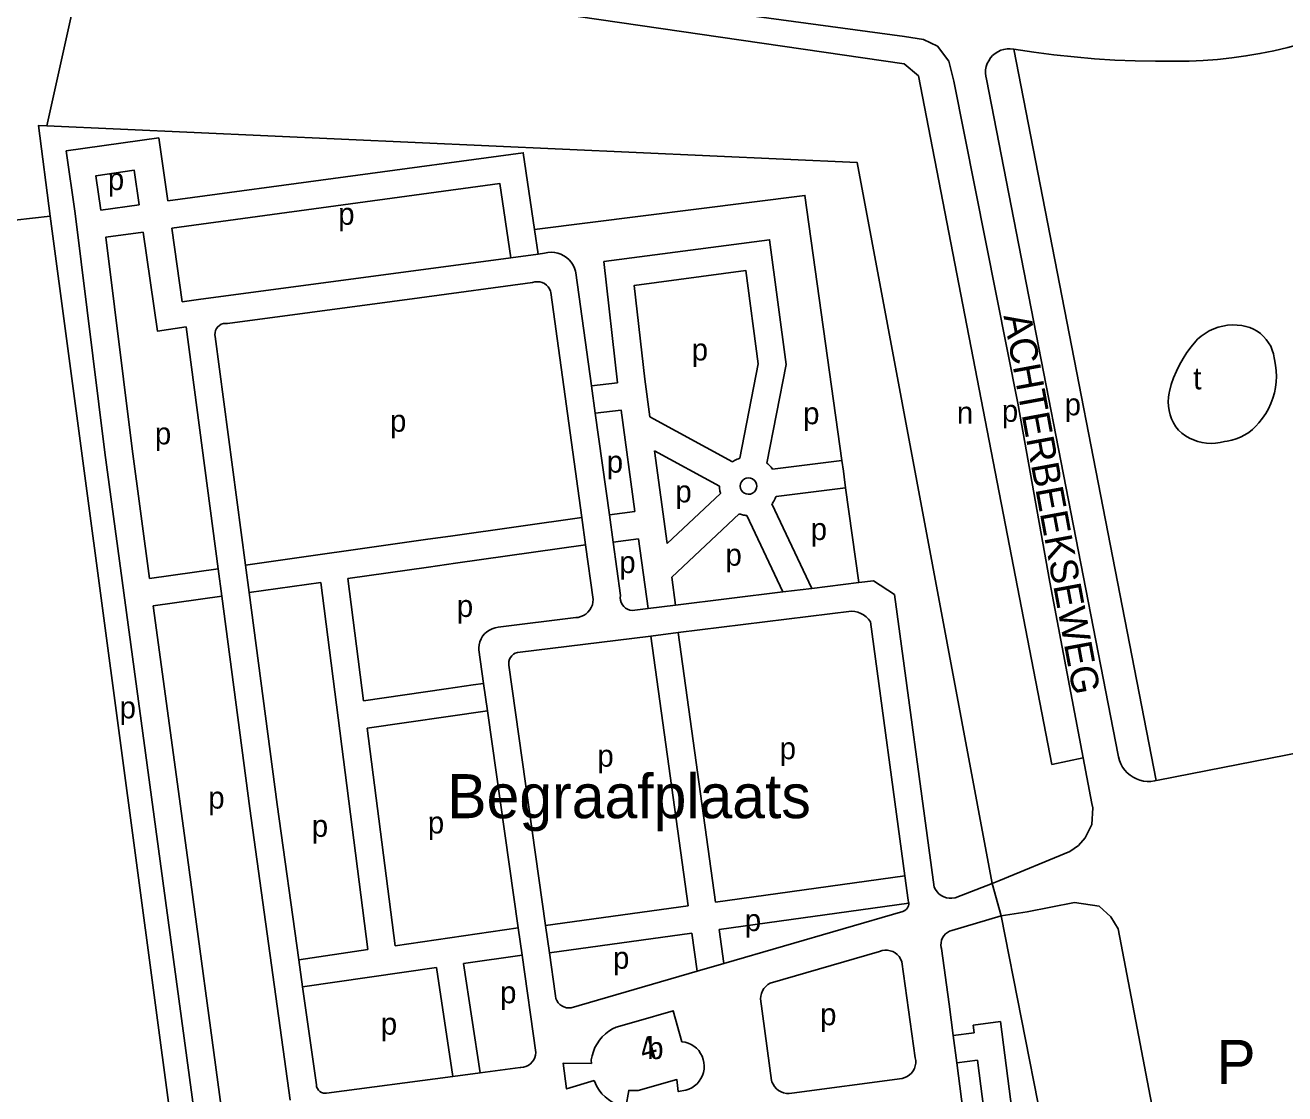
# Model space of a CAD drawing. Extents: x 161093 to 163177, y 379000 to 380904.
# Drawn here: x 162389.1 to 162617.8, y 379974.6 to 380168.6 of the extents above; entities that cross this region are included whole.
import ezdxf

# ---------------------------------------------------------------- set-up
doc = ezdxf.new("R2010")
doc.units = 0
for name, color, linetype in [('BLT_Basislijn', 7, 'Continuous'), ('BLT_Bebouwing', 7, 'Continuous'), ('BLT_Centroide', 7, 'Continuous'), ('BLT_Huisnummer', 7, 'Continuous'), ('BLT_Straatnaam', 7, 'Continuous'), ('BLT_Tekst_parkeren', 7, 'Continuous'), ('BLT_Terrein_beschrifting', 7, 'Continuous')]:
    doc.layers.add(name, color=color, linetype=linetype)

msp = doc.modelspace()

# ---------------------------------------------------------------- linework, layer by layer
at = {"layer": 'BLT_Basislijn'}
for p, q in [((162393.01, 380150.32), (162399.89, 380181.38)), ((162568.58, 380164.26), (162594.45, 380031.45)), ((162563.63, 380158.8), (162587.53, 380036.08)), ((162356.72, 380129.99), (162393.61, 380133.91)), ((162393.61, 380133.91), (162426.07, 379890.63)), ((162481.58, 380131.49), (162482.24, 380127.06)), ((162477.28, 380126.39), (162482.24, 380127.06)), ((162482.24, 380127.06), (162483.39, 380127.21)), ((162420.51, 380118.81), (162477.28, 380126.39)), ((162489.08, 380123.66), (162491.92, 380103.11)), ((162460.67, 380119.12), (162481.21, 380121.88)), ((162484.53, 380120.06), (162490.16, 380079.23)), ((162425.83, 380114.44), (162455.71, 380118.45)), ((162455.71, 380118.45), (162460.67, 380119.12)), ((162418.3, 380113.85), (162424.11, 380069.88)), ((162423.58, 380112.08), (162429.06, 380070.55)), ((162527.23, 380106.99), (162523.77, 380089.07)), ((162501.58, 380104.32), (162502.51, 380097.5)), ((162491.92, 380103.11), (162496.62, 380103.7)), ((162491.92, 380103.11), (162492.6, 380098.15)), ((162492.6, 380098.15), (162495.15, 380079.68)), ((162403.52, 380091.01), (162413.58, 380016.82)), ((162408.47, 380091.69), (162411.66, 380068.17)), ((162490.16, 380079.23), (162466.73, 380075.9)), ((162490.16, 380079.23), (162490.84, 380074.27)), ((162495.15, 380079.68), (162499.8, 380080.31)), ((162495.15, 380079.68), (162495.83, 380074.73)), ((162461.78, 380075.2), (162429.06, 380070.55)), ((162461.78, 380075.2), (162466.73, 380075.9)), ((162490.84, 380074.27), (162467.23, 380070.92)), ((162490.84, 380074.27), (162492.21, 380064.35)), ((162495.83, 380074.73), (162500.47, 380075.35)), ((162495.83, 380074.73), (162497.17, 380065.03)), ((162500.47, 380075.35), (162502.2, 380062.67)), ((162424.11, 380069.88), (162411.66, 380068.17)), ((162424.11, 380069.88), (162424.76, 380064.93)), ((162429.06, 380070.55), (162429.72, 380065.6)), ((162462.28, 380070.22), (162447.68, 380068.15)), ((162462.28, 380070.22), (162467.23, 380070.92)), ((162442.73, 380067.44), (162429.72, 380065.6)), ((162442.73, 380067.44), (162451.31, 380000.75)), ((162447.68, 380068.15), (162450.53, 380045.95)), ((162531.89, 380066.35), (162540.46, 380067.41)), ((162540.46, 380067.41), (162543.09, 380067.74)), ((162543.09, 380067.74), (162546.93, 380065.21)), ((162429.72, 380065.6), (162434.8, 380027.08)), ((162507.16, 380063.29), (162526.68, 380065.71)), ((162526.68, 380065.71), (162528.77, 380065.96)), ((162528.77, 380065.96), (162529.8, 380066.09)), ((162529.8, 380066.09), (162531.89, 380066.35)), ((162546.93, 380065.21), (162554.13, 380012.11)), ((162424.76, 380064.93), (162412.33, 380063.21)), ((162412.33, 380063.21), (162418.54, 380017.49)), ((162424.76, 380064.93), (162429.85, 380026.4)), ((162499.78, 380062.37), (162502.2, 380062.67)), ((162502.2, 380062.67), (162507.16, 380063.29)), ((162474.94, 380059.29), (162489.04, 380061.04)), ((162507.66, 380058.31), (162539.15, 380062.21)), ((162502.69, 380057.69), (162507.66, 380058.31)), ((162507.66, 380058.31), (162514.4, 380009.39)), ((162542.56, 380060.28), (162548.81, 380014.13)), ((162478.45, 380054.69), (162502.69, 380057.69)), ((162502.69, 380057.69), (162509.44, 380008.7)), ((162472.32, 380049.08), (162471.46, 380055.17)), ((162483.58, 380005.14), (162476.9, 380052.43)), ((162472.32, 380049.08), (162470.43, 380048.81)), ((162473.02, 380044.14), (162472.32, 380049.08)), ((162465.49, 380048.1), (162450.53, 380045.95)), ((162465.49, 380048.1), (162470.43, 380048.81)), ((162473.02, 380044.14), (162451.17, 380040.99)), ((162478.59, 380004.7), (162473.02, 380044.14)), ((162451.17, 380040.99), (162456.26, 380001.47)), ((162582.76, 380027.31), (162581.2, 380035.59)), ((162594.8, 380031.54), (162594.45, 380031.45)), ((162429.85, 380026.4), (162437.2, 379973.41)), ((162434.8, 380027.08), (162438.75, 379998.93)), ((162418.54, 380017.49), (162424.67, 379972.19)), ((162548.81, 380014.13), (162514.4, 380009.39)), ((162548.81, 380014.13), (162549.41, 380009.71)), ((162564.67, 380012.78), (162557.94, 380010.17)), ((162565.87, 380013.25), (162564.67, 380012.78)), ((162564.67, 380012.78), (162566.32, 380006.89)), ((162509.44, 380008.7), (162483.58, 380005.14)), ((162549.51, 380009.18), (162515.08, 380004.43)), ((162548.44, 380007.68), (162515.93, 379998.25)), ((162566.32, 380006.89), (162557.37, 380004.24)), ((162566.32, 380006.89), (162582.22, 379925.74)), ((162478.59, 380004.7), (162456.26, 380001.47)), ((162479.29, 379999.75), (162478.59, 380004.7)), ((162484.28, 380000.19), (162483.58, 380005.14)), ((162510.12, 380003.75), (162484.28, 380000.19)), ((162510.12, 380003.75), (162511.08, 379996.84)), ((162515.08, 380004.43), (162515.93, 379998.25)), ((162556.84, 379990.86), (162555.48, 380000.94)), ((162451.31, 380000.75), (162438.75, 379998.93)), ((162438.75, 379998.93), (162439.45, 379993.98)), ((162479.29, 379999.75), (162468.69, 379998.22)), ((162481.79, 379982.08), (162479.29, 379999.75)), ((162485.33, 379992.78), (162484.28, 380000.19)), ((162524.38, 379994.67), (162544.19, 380000.42)), ((162463.74, 379997.5), (162439.45, 379993.98)), ((162463.74, 379997.5), (162466.74, 379977.73)), ((162468.69, 379998.22), (162471.7, 379978.39)), ((162511.08, 379996.84), (162488.22, 379990.21)), ((162515.93, 379998.25), (162511.08, 379996.84)), ((162548.26, 379998.54), (162550.71, 379981.13)), ((162439.45, 379993.98), (162441.94, 379976.19)), ((162522.62, 379991.79), (162524.6, 379976.99)), ((162556.84, 379990.86), (162557.58, 379985.16)), ((162566.17, 379987.69), (162561.21, 379987.05)), ((162566.17, 379987.69), (162571.89, 379943.06)), ((162557.58, 379985.16), (162561.39, 379985.63)), ((162557.58, 379985.16), (162558.23, 379980.21)), ((162561.21, 379987.05), (162561.39, 379985.63)), ((162558.23, 379980.21), (162562.02, 379980.67)), ((162562.02, 379980.67), (162566.09, 379949.01)), ((162466.74, 379977.73), (162471.7, 379978.39)), ((162471.7, 379978.39), (162478.95, 379979.34)), ((162558.23, 379980.21), (162562.37, 379948.61)), ((162443.76, 379974.71), (162466.74, 379977.73)), ((162548.34, 379977.37), (162528.31, 379974.67))]:
    msp.add_line(p, q, dxfattribs=at)
for points in [[(162581.2, 380035.59), (162575.16, 380067.5), (162569.32, 380100), (162557.73, 380158.47), (162556.8, 380162.08), (162554.73, 380164.8), (162552.18, 380166.04), (162548.77, 380166.55), (162469, 380177.37), (162400.95, 380186.18)], [(162581.2, 380035.59), (162575.52, 380034.39), (162551.3, 380159.41), (162548.68, 380161.62), (162449.03, 380176.12), (162399.89, 380181.38)], [(162600.42, 380162.11), (162603.01, 380162.22), (162605.59, 380162.41), (162608.17, 380162.68), (162610.74, 380163.03), (162613.29, 380163.46), (162615.83, 380163.97), (162618.36, 380164.55), (162620.86, 380165.22), (162623.34, 380165.95), (162625.8, 380166.77), (162628.24, 380167.66), (162630.22, 380168.45)], [(162568.58, 380164.26), (162567.94, 380164.34), (162567.36, 380164.32), (162566.78, 380164.22), (162566.22, 380164.05), (162565.68, 380163.8), (162565.19, 380163.48), (162564.74, 380163.1), (162564.36, 380162.66), (162564.03, 380162.17), (162563.77, 380161.64), (162563.59, 380161.09), (162563.48, 380160.51), (162563.46, 380159.92), (162563.51, 380159.34), (162563.63, 380158.8)], [(162568.58, 380164.26), (162572.23, 380163.71), (162575.89, 380163.24), (162579.56, 380162.84), (162583.24, 380162.53), (162586.92, 380162.29), (162590.61, 380162.14), (162594.3, 380162.06), (162597.99, 380162.07), (162600.42, 380162.11)], [(162393.61, 380133.91), (162391.47, 380150.39), (162393.01, 380150.32)], [(162393.01, 380150.32), (162540.14, 380143.69), (162564.67, 380012.78)], [(162414.97, 380136.7), (162413.33, 380148.15), (162396.53, 380145.77)], [(162396.53, 380145.77), (162398.12, 380134.41)], [(162414.97, 380136.7), (162479.51, 380145.46), (162481.58, 380131.49)], [(162409.75, 380135.99), (162408.84, 380142.29), (162401.91, 380141.29), (162402.78, 380135.04)], [(162415.68, 380131.75), (162475.29, 380139.84), (162477.28, 380126.39)], [(162402.78, 380135.04), (162409.75, 380135.99)], [(162481.58, 380131.49), (162530.67, 380137.69), (162537.37, 380089.6)], [(162403.52, 380091.01), (162398.12, 380134.41)], [(162417.6, 380118.38), (162415.68, 380131.75)], [(162408.47, 380091.69), (162403.7, 380130.12), (162410.51, 380131.05)], [(162410.51, 380131.05), (162413.07, 380113.07), (162418.3, 380113.85)], [(162496.62, 380103.7), (162494.17, 380125.68), (162524.26, 380129.66), (162527.23, 380106.99)], [(162483.39, 380127.21), (162483.98, 380127.34), (162484.59, 380127.38), (162485.19, 380127.34), (162485.78, 380127.22), (162486.35, 380127.03), (162486.89, 380126.76), (162487.39, 380126.42), (162487.85, 380126.02), (162488.24, 380125.57), (162488.57, 380125.06), (162488.83, 380124.52), (162489.02, 380123.94), (162489.08, 380123.66)], [(162518.83, 380089.99), (162522.17, 380107.11), (162519.95, 380124.05), (162499.68, 380121.37), (162501.58, 380104.32)], [(162481.21, 380121.88), (162481.64, 380121.99), (162482.09, 380122.03), (162482.54, 380121.99), (162482.97, 380121.87), (162483.37, 380121.68), (162483.73, 380121.42), (162484.04, 380121.09), (162484.29, 380120.72), (162484.46, 380120.31), (162484.53, 380120.06)], [(162420.51, 380118.81), (162417.6, 380118.38)], [(162425.83, 380114.44), (162425.44, 380114.47), (162425.05, 380114.43), (162424.67, 380114.3), (162424.33, 380114.11), (162424.04, 380113.85), (162423.8, 380113.53), (162423.63, 380113.18), (162423.54, 380112.79), (162423.53, 380112.4), (162423.58, 380112.08)], [(162601.97, 380111.58), (162602.64, 380112.15), (162603.35, 380112.65), (162604.1, 380113.1), (162604.9, 380113.47), (162605.72, 380113.76), (162606.57, 380113.98), (162607.43, 380114.12), (162608.3, 380114.18), (162609.18, 380114.17), (162610.03, 380114.07)], [(162610.03, 380114.07), (162610.75, 380113.93), (162611.46, 380113.71), (162612.14, 380113.41), (162612.79, 380113.05), (162613.39, 380112.61), (162613.94, 380112.11), (162614.44, 380111.56), (162614.87, 380110.96), (162615.24, 380110.31), (162615.53, 380109.63), (162615.75, 380108.92), (162615.89, 380108.19), (162615.93, 380107.88)], [(162596.85, 380102.11), (162597.2, 380103.37), (162597.62, 380104.6), (162598.12, 380105.8), (162598.69, 380106.97), (162599.33, 380108.1), (162600.04, 380109.19), (162600.81, 380110.23), (162601.65, 380111.23), (162601.97, 380111.58)], [(162615.93, 380107.88), (162616.12, 380106.88), (162616.24, 380105.87), (162616.28, 380104.85), (162616.24, 380103.84), (162616.12, 380102.83), (162615.91, 380101.83), (162615.63, 380100.86), (162615.28, 380099.9), (162614.85, 380098.98), (162614.35, 380098.1), (162613.78, 380097.26), (162613.12, 380096.43)], [(162598.51, 380095.06), (162598.02, 380095.7), (162597.61, 380096.39), (162597.26, 380097.11), (162596.99, 380097.87), (162596.79, 380098.65), (162596.67, 380099.44), (162596.63, 380100.25), (162596.67, 380101.05), (162596.79, 380101.85), (162596.85, 380102.11)], [(162492.6, 380098.15), (162497.29, 380098.74), (162499.8, 380080.31)], [(162502.51, 380097.5), (162517.5, 380089.35)], [(162606.86, 380093.04), (162606.06, 380092.84), (162605.25, 380092.72), (162604.43, 380092.68), (162603.61, 380092.71), (162602.79, 380092.83), (162601.99, 380093.02), (162601.21, 380093.3), (162600.47, 380093.64), (162599.76, 380094.06), (162599.09, 380094.54), (162598.51, 380095.06)], [(162613.12, 380096.43), (162612.56, 380095.78), (162611.93, 380095.2), (162611.26, 380094.67), (162610.54, 380094.21), (162609.77, 380093.82), (162608.98, 380093.5), (162608.16, 380093.26), (162607.32, 380093.1), (162606.86, 380093.04)], [(162503.35, 380091.32), (162505.64, 380074.48)], [(162503.35, 380091.32), (162515.14, 380084.93)], [(162517.5, 380089.35), (162517.68, 380089.46), (162517.88, 380089.58), (162518.09, 380089.69), (162518.33, 380089.8), (162518.58, 380089.9), (162518.83, 380089.99)], [(162523.77, 380089.07), (162523.9, 380088.96), (162523.99, 380088.88), (162524.11, 380088.77), (162524.21, 380088.66), (162524.34, 380088.54), (162524.51, 380088.34), (162524.65, 380088.16), (162524.78, 380087.99)], [(162524.78, 380087.99), (162537.37, 380089.6)], [(162537.37, 380089.6), (162537.64, 380087.62)], [(162521.92, 380084.92), (162521.88, 380085.27), (162521.75, 380085.62), (162521.51, 380085.96), (162521.17, 380086.22), (162520.77, 380086.38), (162520.36, 380086.42), (162519.99, 380086.36), (162519.67, 380086.22), (162519.4, 380086.02), (162519.15, 380085.72), (162518.98, 380085.35), (162518.92, 380084.92), (162518.98, 380084.5), (162519.15, 380084.13), (162519.4, 380083.83), (162519.67, 380083.63), (162519.99, 380083.49), (162520.36, 380083.43), (162520.77, 380083.47), (162521.17, 380083.63), (162521.51, 380083.89), (162521.75, 380084.23), (162521.88, 380084.58), (162521.92, 380084.92)], [(162537.64, 380087.62), (162537.78, 380086.61)], [(162537.78, 380086.61), (162538.06, 380084.63)], [(162515.32, 380083.59), (162505.64, 380074.48)], [(162515.14, 380084.93), (162515.15, 380084.78), (162515.16, 380084.6), (162515.18, 380084.42), (162515.2, 380084.2), (162515.24, 380083.99), (162515.27, 380083.82), (162515.31, 380083.67), (162515.32, 380083.59)], [(162538.06, 380084.63), (162525.42, 380083.04)], [(162538.06, 380084.63), (162540.46, 380067.41)], [(162525.42, 380083.04), (162525.34, 380082.86), (162525.26, 380082.65), (162525.14, 380082.42), (162525.01, 380082.18), (162524.85, 380081.93), (162524.75, 380081.79), (162524.68, 380081.7)], [(162524.68, 380081.7), (162531.89, 380066.35)], [(162506.47, 380068.39), (162518.71, 380079.88)], [(162518.71, 380079.88), (162518.82, 380079.85), (162518.96, 380079.8), (162519.12, 380079.76), (162519.31, 380079.71), (162519.51, 380079.67), (162519.73, 380079.64), (162519.95, 380079.61), (162520.13, 380079.6)], [(162520.13, 380079.6), (162526.68, 380065.71)], [(162506.47, 380068.39), (162507.16, 380063.29)], [(162497.17, 380065.03), (162497.13, 380064.61), (162497.18, 380064.18), (162497.31, 380063.77), (162497.51, 380063.39), (162497.77, 380063.05), (162498.1, 380062.78), (162498.47, 380062.56), (162498.87, 380062.42), (162499.3, 380062.35), (162499.78, 380062.37)], [(162492.21, 380064.35), (162492.17, 380063.84), (162492.06, 380063.34), (162491.87, 380062.86), (162491.6, 380062.43), (162491.27, 380062.03), (162490.89, 380061.69), (162490.45, 380061.42), (162489.98, 380061.22), (162489.49, 380061.09), (162489.04, 380061.04)], [(162539.15, 380062.21), (162539.72, 380062.16), (162540.29, 380062.02), (162540.82, 380061.81), (162541.33, 380061.53), (162541.79, 380061.18), (162542.19, 380060.77), (162542.56, 380060.28)], [(162474.94, 380059.29), (162474.39, 380059.2), (162473.86, 380059.03), (162473.36, 380058.78), (162472.9, 380058.46), (162472.49, 380058.09), (162472.14, 380057.65), (162471.86, 380057.17), (162471.65, 380056.66), (162471.51, 380056.12), (162471.45, 380055.57), (162471.46, 380055.17)], [(162478.45, 380054.69), (162478.07, 380054.58), (162477.72, 380054.39), (162477.42, 380054.13), (162477.18, 380053.82), (162477, 380053.47), (162476.89, 380053.09), (162476.87, 380052.69), (162476.9, 380052.43)], [(162594.45, 380031.45), (162594.15, 380031.38), (162593.49, 380031.3), (162592.81, 380031.29), (162592.15, 380031.36), (162591.49, 380031.52), (162590.86, 380031.75), (162590.26, 380032.05), (162589.71, 380032.43), (162589.2, 380032.86), (162588.74, 380033.36), (162588.35, 380033.9), (162588.02, 380034.49), (162587.77, 380035.11), (162587.59, 380035.76), (162587.53, 380036.08)], [(162624.7, 379997.35), (162625.43, 380015.79), (162621.09, 380036.66), (162594.8, 380031.54)], [(162565.87, 380013.25), (162578.76, 380018.55), (162580.34, 380019.69), (162581.54, 380021.05), (162582.79, 380023.47), (162582.92, 380026.48), (162582.76, 380027.31)], [(162413.58, 380016.82), (162430.02, 379895.42), (162476.37, 379901.36)], [(162554.13, 380012.11), (162554.36, 380011.66), (162554.65, 380011.24), (162555.01, 380010.88), (162555.42, 380010.57), (162555.87, 380010.34), (162556.35, 380010.17), (162556.85, 380010.09), (162557.36, 380010.08), (162557.94, 380010.17)], [(162549.51, 380009.18), (162549.52, 380009.02), (162549.45, 380008.68), (162549.3, 380008.36), (162549.09, 380008.08), (162548.82, 380007.86), (162548.44, 380007.68)], [(162549.41, 380009.71), (162549.5, 380009.37), (162549.51, 380009.18)], [(162566.32, 380006.89), (162571, 380007.59), (162579.61, 380009.3), (162584.07, 380008.64), (162586.19, 380006.73), (162587.57, 380004.53), (162600, 379939.37), (162603.75, 379919.71)], [(162557.37, 380004.24), (162556.93, 380004.1), (162556.53, 380003.89), (162556.18, 380003.61), (162555.87, 380003.27), (162555.63, 380002.88), (162555.47, 380002.46), (162555.38, 380002.01), (162555.37, 380001.56), (162555.43, 380001.11), (162555.48, 380000.94)], [(162544.19, 380000.42), (162544.66, 380000.57), (162545.15, 380000.65), (162545.64, 380000.64), (162546.13, 380000.55), (162546.6, 380000.39), (162547.03, 380000.15), (162547.42, 379999.85), (162547.75, 379999.49), (162548.03, 379999.08), (162548.26, 379998.54)], [(162522.62, 379991.79), (162522.66, 379992.3), (162522.77, 379992.79), (162522.97, 379993.26), (162523.23, 379993.69), (162523.56, 379994.08), (162523.94, 379994.41), (162524.38, 379994.67)], [(162485.33, 379992.78), (162485.34, 379992.34), (162485.44, 379991.9), (162485.61, 379991.49), (162485.85, 379991.12), (162486.15, 379990.8), (162486.51, 379990.53), (162486.91, 379990.34), (162487.34, 379990.21), (162487.78, 379990.17), (162488.22, 379990.21)], [(162481.79, 379982.08), (162481.74, 379981.61), (162481.61, 379981.16), (162481.41, 379980.73), (162481.14, 379980.35), (162480.81, 379980.01), (162480.42, 379979.74), (162480, 379979.53), (162479.54, 379979.4), (162479.07, 379979.34), (162478.95, 379979.34)], [(162550.71, 379981.13), (162550.79, 379980.64), (162550.79, 379980.14), (162550.71, 379979.65), (162550.56, 379979.18), (162550.33, 379978.74), (162550.03, 379978.35), (162549.67, 379978), (162549.26, 379977.72), (162548.82, 379977.51), (162548.34, 379977.37)], [(162441.94, 379976.19), (162441.99, 379975.84), (162442.13, 379975.51), (162442.33, 379975.22), (162442.59, 379974.98), (162442.9, 379974.81), (162443.23, 379974.71), (162443.59, 379974.69), (162443.76, 379974.71)], [(162528.31, 379974.67), (162527.81, 379974.62), (162527.3, 379974.64), (162526.8, 379974.75), (162526.33, 379974.93), (162525.89, 379975.18), (162525.49, 379975.5), (162525.15, 379975.88), (162524.87, 379976.3), (162524.67, 379976.77), (162524.6, 379976.99)]]:
    msp.add_lwpolyline(points, dxfattribs=at)
at = {"layer": 'BLT_Bebouwing'}
for p, q in [((162496.4, 379986.7), (162500, 379987.73)), ((162491.88, 379980.09), (162491.85, 379980.68)), ((162492.85, 379975.89), (162492.4, 379976.98))]:
    msp.add_line(p, q, dxfattribs=at)
for points in [[(162508.89, 379983.94), (162508.32, 379984.03), (162506.71, 379989.65), (162500, 379987.73)], [(162496.4, 379986.7), (162495.7, 379986.35), (162495.04, 379985.93), (162494.42, 379985.45), (162493.86, 379984.91), (162493.35, 379984.31), (162492.91, 379983.66), (162492.54, 379982.97), (162492.24, 379982.24), (162492.01, 379981.49), (162491.86, 379980.73), (162491.85, 379980.68)], [(162509.02, 379975.22), (162509.58, 379975.41), (162510.12, 379975.67), (162510.62, 379976), (162511.07, 379976.4), (162511.46, 379976.85), (162511.79, 379977.35), (162512.05, 379977.89), (162512.24, 379978.46), (162512.35, 379979.05), (162512.38, 379979.65), (162512.33, 379980.24), (162512.2, 379980.83), (162511.99, 379981.39), (162511.71, 379981.92), (162511.37, 379982.41), (162510.96, 379982.84), (162510.49, 379983.22), (162509.98, 379983.54), (162509.44, 379983.78), (162508.89, 379983.94)], [(162491.88, 379980.09), (162486.76, 379980.11), (162487.39, 379975.47), (162492.4, 379976.98)], [(162492.85, 379975.89), (162493.29, 379975.22), (162493.8, 379974.59), (162494.37, 379974.02), (162495, 379973.51), (162495.67, 379973.06), (162496.38, 379972.68), (162497.13, 379972.37), (162497.22, 379972.34)], [(162500, 379975.16), (162500.4, 379975.16), (162507.42, 379977.16), (162507.65, 379974.99), (162509.02, 379975.22)], [(162500, 379975.16), (162498.68, 379975.18), (162498.15, 379972.12), (162497.22, 379972.34)]]:
    msp.add_lwpolyline(points, dxfattribs=at)

# ---------------------------------------------------------------- texts
at = {"layer": 'BLT_Centroide'}
for s, p in [('p', (162404.08, 380138.67)), ('p', (162445.91, 380132.37)), ('p', (162510.1, 380107.73)), ('t', (162601.18, 380102.49)), ('p', (162530.34, 380096.15)), ('n', (162558.25, 380096.26)), ('p', (162566.43, 380096.59)), ('p', (162577.82, 380097.77)), ('p', (162455.31, 380094.79)), ('p', (162412.62, 380092.49)), ('p', (162494.67, 380087.36)), ('p', (162507.13, 380081.96)), ('p', (162531.71, 380075.13)), ('p', (162496.95, 380069.12)), ('p', (162516.24, 380070.47)), ('p', (162467.45, 380061.16)), ('p', (162406.21, 380042.74)), ('p', (162526.07, 380035.32)), ('p', (162492.97, 380033.97)), ('p', (162422.31, 380026.36)), ('p', (162441.11, 380021.23)), ('p', (162462.19, 380021.84)), ('p', (162519.74, 380004.12)), ('p', (162495.81, 379997.28)), ('p', (162475.3, 379991.01)), ('p', (162533.42, 379987.02)), ('p', (162453.65, 379985.31)), ('b', (162502.03, 379980.88))]:
    msp.add_text(s, height=4, dxfattribs=at).set_placement(p)
at = {"layer": 'BLT_Huisnummer'}
msp.add_text('4', height=4, rotation=15.9465, dxfattribs=at).set_placement((162501.3, 379980.61))
at = {"layer": 'BLT_Straatnaam'}
msp.add_text('ACHTERBEEKSEWEG', height=5, rotation=280.4399, dxfattribs=at).set_placement((162566.71, 380115.83))
at = {"layer": 'BLT_Tekst_parkeren'}
msp.add_text('P', height=8, dxfattribs=at).set_placement((162605.38, 379976.36))
at = {"layer": 'BLT_Terrein_beschrifting'}
msp.add_text('Begraafplaats', height=8, dxfattribs=at).set_placement((162465.72, 380024.62))

doc.saveas('drawing.dxf')
